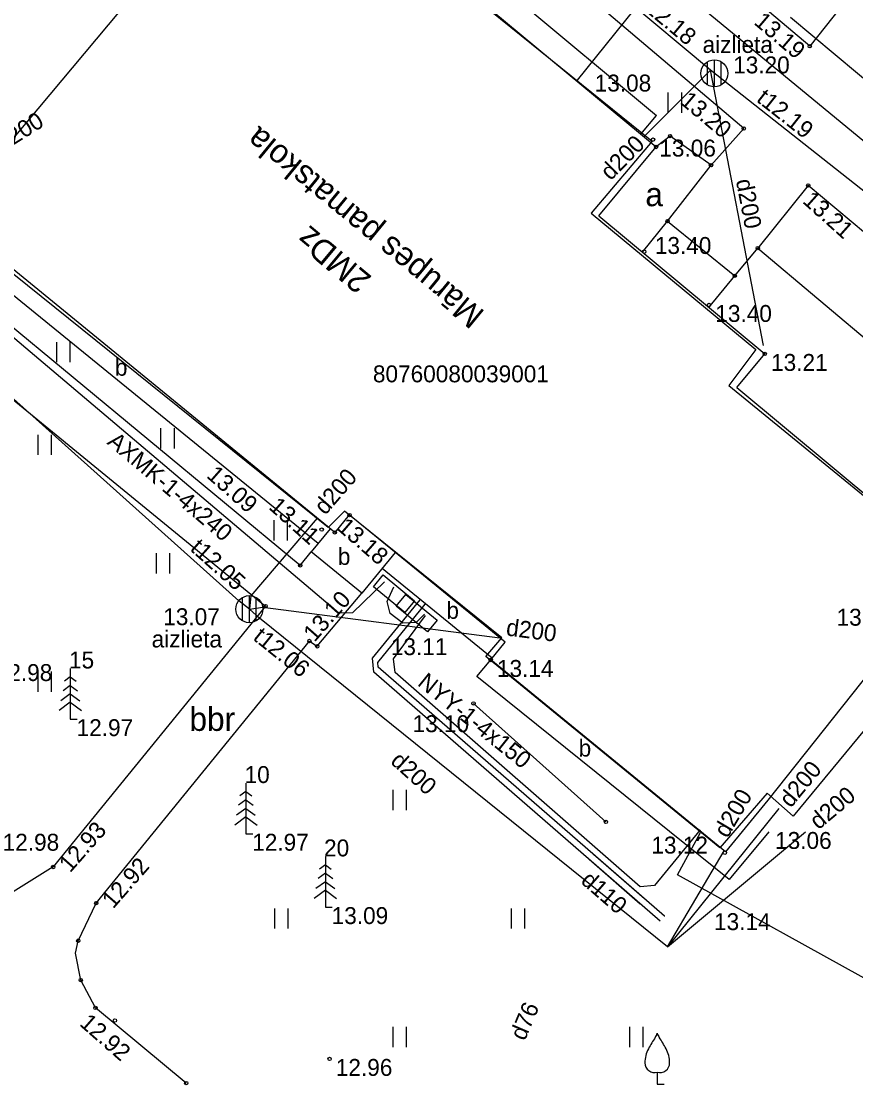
# Model space of a CAD drawing. Extents: x 503877 to 504025, y 304562 to 304725.
# Drawn here: x 503933 to 503957.69, y 304561.89 to 304593.32 of the extents above; entities that cross this region are included whole.
import ezdxf

# ---------------------------------------------------------------- set-up
doc = ezdxf.new("R2010")
doc.units = 0
for name, color, linetype in [('41', 7, 'Continuous'), ('42', 7, 'Continuous'), ('APGS_VADP_ZSPR_####_#', 7, 'Continuous'), ('BUVE_BDET_####_####_#', 7, 'Continuous'), ('BUVE_BDET_####_TKST_#', 7, 'Continuous'), ('BUVE_EKAS_####_####_#', 7, 'Continuous'), ('BUVE_EKAS_ADRS_TKST_#', 7, 'Continuous'), ('BUVE_EKAS_BIZM_TKST_#', 7, 'Continuous'), ('CELI_CMAL_####_####_#', 7, 'Continuous'), ('CELI_CSEG_####_TKST_#', 7, 'Continuous'), ('ELEK_ACRL_####_####_#', 7, 'Continuous'), ('ELEK_ELEM_####_####_#', 7, 'Continuous'), ('ELEK_VADP_ZSPR_####_#', 7, 'Continuous'), ('ELEK_VADP_ZSPR_TKST_#', 7, 'Continuous'), ('LKAN_ELEM_####_####_#', 7, 'Continuous'), ('LKAN_ELEM_PAST_TKST_#', 7, 'Continuous'), ('LKAN_VADP_PAST_####_#', 7, 'Continuous'), ('LKAN_VADP_PAST_TKST_#', 7, 'Continuous'), ('RELJ_AATZ_####_TKST_#', 7, 'Continuous'), ('RELJ_ELEM_####_####_#', 7, 'Continuous'), ('SAKT_VADP_KABE_####_#', 7, 'Continuous'), ('SILT_VADP_NEDR_TKST_#', 7, 'Continuous'), ('SKAN_ELEM_PAST_TKST_#', 7, 'Continuous'), ('SKAN_VADP_PAST_####_#', 7, 'Continuous'), ('TERT_DIAM_####_TKST_#', 7, 'Continuous'), ('TERT_ELEM_####_####_#', 7, 'Continuous'), ('TERT_KRND_####_####_#', 7, 'Continuous'), ('UDTK_VADP_NEDR_####_#', 7, 'Continuous')]:
    doc.layers.add(name, color=color, linetype=linetype)

msp = doc.modelspace()

# ---------------------------------------------------------------- linework, layer by layer
at = {"layer": '42'}
msp.add_lwpolyline([(503940.294, 304598.947), (503951.661, 304589.773), (503949.864, 304587.645), (503954.733, 304583.621), (503953.927, 304582.557), (503960.49, 304577.208), (503958.987, 304575.41), (503959.865, 304574.697), (503955.838, 304569.828), (503955.063, 304570.502), (503953.67, 304568.891), (503946.74, 304574.542), (503947.217, 304575.092), (503942.561, 304578.835), (503942.084, 304578.358), (503930.754, 304587.457), (503939.344, 304597.708)], close=True, dxfattribs=at)
at = {"layer": 'APGS_VADP_ZSPR_####_#'}
msp.add_line((503955.752, 304593.437), (503977.746, 304575.06), dxfattribs=at)
at = {"layer": 'BUVE_BDET_####_####_#'}
for p, q in [((503941.373, 304599.205), (503951.794, 304590.537)), ((503951.33, 304589.979), (503951.794, 304590.537)), ((503951.375, 304586.496), (503952.12, 304587.412)), ((503952.12, 304587.412), (503954.107, 304585.796)), ((503941.788, 304577.888), (503930.703, 304586.889)), ((503953.345, 304584.859), (503954.107, 304585.796)), ((503942.142, 304578.321), (503941.582, 304577.635)), ((503943.08, 304576.412), (503941.582, 304577.635)), ((503944.066, 304577.619), (503943.08, 304576.412)), ((503946.931, 304574.493), (503943.681, 304577.147)), ((503946.483, 304573.952), (503946.888, 304574.441)), ((503953.94, 304567.957), (503946.483, 304573.952)), ((503955.114, 304569.357), (503953.94, 304567.957))]:
    msp.add_line(p, q, dxfattribs=at)
at = {"layer": 'BUVE_EKAS_####_####_#'}
for p, q in [((503940.557, 304598.938), (503951.781, 304589.603)), ((503950.088, 304587.567), (503951.781, 304589.603)), ((503950.088, 304587.567), (503954.995, 304583.486)), ((503942.277, 304578.21), (503931.011, 304587.412)), ((503954.167, 304582.49), (503954.995, 304583.486)), ((503954.167, 304582.49), (503960.588, 304577.15)), ((503942.703, 304578.732), (503942.277, 304578.21)), ((503947.316, 304574.965), (503942.703, 304578.732)), ((503959.271, 304575.566), (503955.082, 304570.298)), ((503946.888, 304574.441), (503947.316, 304574.965)), ((503953.833, 304568.769), (503946.888, 304574.441)), ((503955.082, 304570.298), (503953.833, 304568.769))]:
    msp.add_line(p, q, dxfattribs=at)
at = {"layer": 'CELI_CMAL_####_####_#'}
for p, q in [((503956.326, 304592.583), (503942.956, 304603.993)), ((503954.372, 304590.15), (503943.33, 304599.524)), ((503957.88, 304594.554), (503956.326, 304592.583)), ((503953.405, 304589.062), (503954.372, 304590.15)), ((503952.195, 304589.924), (503951.781, 304589.603)), ((503953.405, 304589.062), (503952.195, 304589.924)), ((503952.12, 304587.412), (503953.405, 304589.062)), ((503956.281, 304588.468), (503954.789, 304586.616)), ((503965.285, 304580.881), (503956.281, 304588.468)), ((503941.255, 304577.235), (503930.227, 304586.356)), ((503954.107, 304585.796), (503954.789, 304586.616)), ((503954.789, 304586.616), (503963.685, 304579.115)), ((503929.16, 304585.083), (503940.23, 304576.035)), ((503941.255, 304577.235), (503941.582, 304577.635)), ((503941.758, 304574.845), (503943.08, 304576.412)), ((503940.23, 304576.035), (503933.951, 304568.323)), ((503935.224, 304567.257), (503941.526, 304575.002)), ((503941.526, 304575.002), (503941.758, 304574.845)), ((503933.951, 304568.323), (503932.691, 304567.544)), ((503934.69, 304566.145), (503935.224, 304567.257)), ((503934.607, 304565.771), (503934.69, 304566.145)), ((503934.764, 304564.981), (503934.607, 304565.771)), ((503935.2, 304564.158), (503934.764, 304564.981)), ((503937.885, 304561.937), (503935.2, 304564.158))]:
    msp.add_line(p, q, dxfattribs=at)
at = {"layer": 'ELEK_ACRL_####_####_#'}
for p, q in [((503949.798, 304568.55), (503951.308, 304567.238)), ((503949.929, 304568.701), (503951.439, 304567.389))]:
    msp.add_line(p, q, dxfattribs=at)
at = {"layer": 'ELEK_ELEM_####_####_#'}
for points in [[(503943.708, 304576.954), (503944.633, 304576.189), (503944.346, 304575.842), (503943.421, 304576.607)], [(503944.375, 304576.377), (503945.304, 304575.618), (503945.019, 304575.27), (503944.09, 304576.029)]]:
    msp.add_lwpolyline(points, close=True, dxfattribs=at)
at = {"layer": 'ELEK_VADP_ZSPR_####_#'}
for p, q in [((503942.397, 304575.823), (503932.157, 304584.487)), ((503943.752, 304576.749), (503942.798, 304575.835)), ((503943.827, 304576.173), (503944.022, 304576.606)), ((503943.394, 304574.494), (503944.798, 304576.22)), ((503943.549, 304574.367), (503944.953, 304576.094)), ((503943.919, 304575.81), (503943.827, 304576.173)), ((503942.798, 304575.835), (503942.397, 304575.823)), ((503944.294, 304575.526), (503943.919, 304575.81)), ((503944.018, 304574.473), (503944.961, 304575.757)), ((503944.935, 304575.792), (503944.684, 304575.549)), ((503944.684, 304575.549), (503944.294, 304575.526)), ((503943.43, 304574.078), (503943.394, 304574.494)), ((503943.562, 304574.229), (503943.549, 304574.367)), ((503944.062, 304574.069), (503944.018, 304574.473)), ((503951.902, 304566.722), (503943.43, 304574.078)), ((503952.033, 304566.873), (503943.562, 304574.229)), ((503951.305, 304567.736), (503944.062, 304574.069)), ((503953.082, 304569.416), (503951.735, 304567.772)), ((503951.735, 304567.772), (503951.305, 304567.736)), ((503952.034, 304566.873), (503952.033, 304566.873)), ((503951.905, 304566.72), (503951.902, 304566.722))]:
    msp.add_line(p, q, dxfattribs=at)
at = {"layer": 'LKAN_ELEM_####_####_#'}
for p, q in [((503953.305, 304591.433), (503953.305, 304592.125)), ((503953.505, 304591.379), (503953.505, 304592.179)), ((503953.705, 304591.433), (503953.705, 304592.125)), ((503939.551, 304575.597), (503939.551, 304576.289)), ((503939.751, 304575.543), (503939.751, 304576.343)), ((503939.951, 304575.597), (503939.951, 304576.289))]:
    msp.add_line(p, q, dxfattribs=at)
for centre in [(503953.505, 304591.779), (503939.751, 304575.943)]:
    msp.add_circle(centre, 0.4, dxfattribs=at)
at = {"layer": 'LKAN_VADP_PAST_####_#'}
for p, q in [((503953.386, 304591.874), (503942.453, 304601.026)), ((503953.386, 304591.874), (503951.422, 304589.902)), ((503966.208, 304581.751), (503953.386, 304591.874)), ((503954.958, 304583.735), (503953.386, 304591.874)), ((503939.435, 304576.189), (503928.18, 304586.275)), ((503941.759, 304578.633), (503939.792, 304576.341)), ((503939.792, 304576.341), (503939.751, 304575.943)), ((503939.751, 304575.943), (503939.435, 304576.189)), ((503939.751, 304575.943), (503940.147, 304575.999)), ((503939.751, 304575.943), (503940.052, 304575.68)), ((503940.147, 304575.999), (503947.157, 304575.094)), ((503952.113, 304565.96), (503940.052, 304575.68)), ((503955.408, 304570.049), (503952.113, 304565.96)), ((503952.113, 304565.96), (503956.195, 304569.357)), ((503952.113, 304565.96), (503953.792, 304568.802))]:
    msp.add_line(p, q, dxfattribs=at)
at = {"layer": 'RELJ_ELEM_####_####_#'}
for centre in [(503956.326, 304592.583), (503954.372, 304590.15), (503951.69, 304589.821), (503952.195, 304589.924), (503951.781, 304589.603), (503953.405, 304589.062), (503956.281, 304588.468), (503952.12, 304587.412), (503954.789, 304586.616), (503951.428, 304586.509), (503954.107, 304585.796), (503953.346, 304584.933), (503954.995, 304583.486), (503942.712, 304578.725), (503941.89, 304578.296), (503942.277, 304578.21), (503941.255, 304577.235), (503940.23, 304576.035), (503941.526, 304575.002), (503941.758, 304574.845), (503946.888, 304574.441), (503946.38, 304573.157), (503950.297, 304569.655), (503953.814, 304568.746), (503933.951, 304568.323), (503935.224, 304567.257), (503934.69, 304566.145), (503934.764, 304564.981), (503935.2, 304564.158), (503935.776, 304563.785), (503942.122, 304562.649), (503937.885, 304561.937)]:
    msp.add_circle(centre, 0.05, dxfattribs=at)
at = {"layer": 'SAKT_VADP_KABE_####_#'}
for p, q in [((503952.415, 304568.091), (503953.091, 304569.346)), ((503959.129, 304564.37), (503952.415, 304568.091))]:
    msp.add_line(p, q, dxfattribs=at)
at = {"layer": 'SKAN_VADP_PAST_####_#'}
msp.add_line((503971.339, 304578.696), (503938.881, 304605.476), dxfattribs=at)
at = {"layer": 'TERT_ELEM_####_####_#'}
for p, q in [((503952.142, 304590.614), (503952.142, 304591.214)), ((503952.542, 304590.614), (503952.542, 304591.214)), ((503934.052, 304583.239), (503934.052, 304583.839)), ((503934.452, 304583.239), (503934.452, 304583.839)), ((503937.132, 304580.695), (503937.132, 304581.295)), ((503937.532, 304580.695), (503937.532, 304581.295)), ((503933.5, 304580.5), (503933.5, 304581.1)), ((503933.9, 304580.5), (503933.9, 304581.1)), ((503940.481, 304577.972), (503940.481, 304578.572)), ((503940.881, 304577.972), (503940.881, 304578.572)), ((503937, 304577), (503937, 304577.6)), ((503937.4, 304577), (503937.4, 304577.6)), ((503933.5, 304573.5), (503933.5, 304574.1)), ((503933.9, 304573.5), (503933.9, 304574.1)), ((503934.456, 304574.191), (503934.456, 304572.691)), ((503934.456, 304573.941), (503934.28, 304573.813)), ((503934.456, 304573.941), (503934.63, 304573.813)), ((503934.456, 304573.441), (503934.178, 304573.237)), ((503934.456, 304573.691), (503934.24, 304573.533)), ((503934.456, 304573.691), (503934.672, 304573.533)), ((503934.456, 304573.441), (503934.734, 304573.237)), ((503934.456, 304573.191), (503934.124, 304572.947)), ((503934.456, 304573.191), (503934.79, 304572.947)), ((503934.456, 304572.691), (503934.656, 304572.691)), ((503939.649, 304570.804), (503939.649, 304569.304)), ((503944, 304570), (503944, 304570.6)), ((503944.4, 304570), (503944.4, 304570.6)), ((503939.649, 304570.304), (503939.433, 304570.146)), ((503939.649, 304570.554), (503939.473, 304570.426)), ((503939.649, 304570.554), (503939.823, 304570.426)), ((503939.649, 304570.304), (503939.865, 304570.146)), ((503939.649, 304570.054), (503939.371, 304569.85)), ((503939.649, 304570.054), (503939.927, 304569.85)), ((503939.649, 304569.804), (503939.317, 304569.56)), ((503939.649, 304569.804), (503939.983, 304569.56)), ((503939.649, 304569.304), (503939.849, 304569.304)), ((503941.999, 304568.636), (503941.999, 304567.136)), ((503941.999, 304568.136), (503941.783, 304567.978)), ((503941.999, 304568.386), (503941.823, 304568.258)), ((503941.999, 304568.386), (503942.173, 304568.258)), ((503941.999, 304568.136), (503942.215, 304567.978)), ((503941.999, 304567.886), (503941.721, 304567.682)), ((503941.999, 304567.886), (503942.277, 304567.682)), ((503941.999, 304567.636), (503941.667, 304567.392)), ((503941.999, 304567.636), (503942.333, 304567.392)), ((503941.999, 304567.136), (503942.199, 304567.136)), ((503940.5, 304566.5), (503940.5, 304567.1)), ((503940.9, 304566.5), (503940.9, 304567.1)), ((503947.5, 304566.5), (503947.5, 304567.1)), ((503947.9, 304566.5), (503947.9, 304567.1)), ((503944, 304563), (503944, 304563.6)), ((503944.4, 304563), (503944.4, 304563.6)), ((503951, 304563), (503951, 304563.6)), ((503951.4, 304563), (503951.4, 304563.6)), ((503951.815, 304562.258), (503951.815, 304561.906)), ((503951.815, 304561.906), (503952.015, 304561.906))]:
    msp.add_line(p, q, dxfattribs=at)
for centre, radius, start, end in [((503951.398, 304563.544), 0.439, 324.3837, 341.712), ((503952.232, 304563.544), 0.439, 198.288, 215.6163), ((503964.44, 304555.51), 14.88, 148.4844, 149.9901), ((503939.19, 304555.51), 14.88, 30.0099, 31.5156), ((503952.339, 304562.531), 0.89, 151.757, 179.9138), ((503951.291, 304562.531), 0.89, 0.0862, 28.243), ((503951.739, 304562.537), 0.29, 181.0782, 285.2823), ((503951.891, 304562.537), 0.29, 254.7177, 358.9218)]:
    msp.add_arc(centre, radius, start, end, dxfattribs=at)
at = {"layer": 'TERT_KRND_####_####_#'}
msp.add_line((503946.38, 304573.157), (503950.297, 304569.655), dxfattribs=at)
at = {"layer": 'UDTK_VADP_NEDR_####_#'}
msp.add_line((503954.857, 304598.318), (503949.443, 304591.578), dxfattribs=at)

# ---------------------------------------------------------------- texts
at = {"layer": '41'}
msp.add_text('80760080039001', height=0.5, dxfattribs=at).set_placement((503943.405, 304582.648))
at = {"layer": 'BUVE_BDET_####_TKST_#'}
for p in [(503935.775, 304582.842), (503942.367, 304577.251), (503945.578, 304575.657), (503949.49, 304571.587)]:
    msp.add_text('b', height=0.5, dxfattribs=at).set_placement(p)
at = {"layer": 'BUVE_EKAS_ADRS_TKST_#'}
msp.add_text('2MDz', height=0.7, rotation=140.2493, dxfattribs=at).set_placement((503943.4, 304585.759))
at = {"layer": 'BUVE_EKAS_BIZM_TKST_#'}
msp.add_text('Mārupes pamatskola', height=0.7, rotation=140.6136, dxfattribs=at).set_placement((503946.745, 304584.728))
at = {"layer": 'CELI_CSEG_####_TKST_#'}
for s, p in [('a', (503951.462, 304587.853)), ('bbr', (503937.978, 304572.346))]:
    msp.add_text(s, height=0.7, dxfattribs=at).set_placement(p)
at = {"layer": 'ELEK_VADP_ZSPR_TKST_#'}
for s, rotation, p in [('AXMK-1-4x240', 319.7622, (503935.519, 304580.842)), ('NYY-1-4x150', 321.2467, (503944.697, 304573.712)), ('d110', 319.0352, (503949.523, 304567.871))]:
    msp.add_text(s, height=0.5, rotation=rotation, dxfattribs=at).set_placement(p)
at = {"layer": 'LKAN_ELEM_PAST_TKST_#'}
for s, p in [(' 13.20', (503953.874, 304591.779)), (' 13.07', (503937.018, 304575.47))]:
    msp.add_text(s, height=0.5, dxfattribs=at).set_placement(p)
at = {"layer": 'LKAN_VADP_PAST_TKST_#'}
for s, rotation, p in [('t12.18', 320.2454, (503951.273, 304593.767)), ('t12.19', 321.7088, (503954.718, 304590.972)), ('d200', 31.9528, (503932.455, 304589.455)), ('d200', 45.1215, (503950.433, 304588.591)), ('d200', 280.9317, (503954.138, 304588.612)), ('d200', 48.9447, (503941.994, 304578.701)), ('t12.05', 318.1348, (503937.97, 304577.702)), ('d200', 352.6483, (503947.326, 304575.168)), ('t12.06', 321.1343, (503939.83, 304575.062)), ('d200', 318.1348, (503943.897, 304571.408)), ('d200', 50.5433, (503955.762, 304570.046)), ('d200', 59.4736, (503953.889, 304569.151)), ('d200', 39.7641, (503956.582, 304569.406))]:
    msp.add_text(s, height=0.5, rotation=rotation, dxfattribs=at).set_placement(p)
at = {"layer": 'RELJ_AATZ_####_TKST_#'}
for s, rotation, p in [(' 13.19', 319.6269, (503954.505, 304593.375)), (' 13.20', 320.0156, (503952.319, 304591.027)), (' 13.21', 318.152, (503955.947, 304588.096)), (' 13.09', 318.5453, (503938.318, 304579.981)), (' 13.11', 318.2094, (503940.158, 304579.052)), (' 13.18', 319.0555, (503942.178, 304578.436)), (' 13.10', 48.5782, (503941.554, 304574.809)), (' 12.93', 48.5414, (503934.326, 304567.992)), (' 12.92', 48.6625, (503935.599, 304566.927)), (' 12.92', 318.7183, (503934.56, 304563.782))]:
    msp.add_text(s, height=0.5, rotation=rotation, dxfattribs=at).set_placement(p)
for s, p in [(' 13.08', (503949.778, 304591.243)), (' 13.06', (503951.69, 304589.321)), (' 13.40', (503951.557, 304586.442)), (' 13.40', (503953.346, 304584.433)), (' 13.21', (503954.995, 304582.986)), (' 13.22', (503956.932, 304575.455)), (' 13.11', (503943.749, 304574.584)), (' 13.14', (503946.888, 304573.941)), (' 12.98', (503932.064, 304573.819)), (' 13.10', (503944.393, 304572.308)), (' 12.97', (503934.456, 304572.191)), (' 13.06', (503955.114, 304568.857)), (' 12.98', (503932.268, 304568.804)), (' 12.97', (503939.649, 304568.804)), (' 13.12', (503951.455, 304568.719)), (' 13.09', (503941.999, 304566.636)), (' 13.14', (503953.308, 304566.457)), (' 12.96', (503942.122, 304562.149))]:
    msp.add_text(s, height=0.5, dxfattribs=at).set_placement(p)
at = {"layer": 'SILT_VADP_NEDR_TKST_#'}
msp.add_text('d76', height=0.5, rotation=66.9335, dxfattribs=at).set_placement((503947.896, 304563.162))
at = {"layer": 'SKAN_ELEM_PAST_TKST_#'}
for p in [(503953.155, 304592.383), (503936.861, 304574.811)]:
    msp.add_text('aizlieta', height=0.5, dxfattribs=at).set_placement(p)
at = {"layer": 'TERT_DIAM_####_TKST_#'}
for s, p in [(' 15', (503934.231, 304574.191)), (' 10', (503939.424, 304570.804)), (' 20', (503941.774, 304568.636))]:
    msp.add_text(s, height=0.5, dxfattribs=at).set_placement(p)

doc.saveas('drawing.dxf')
